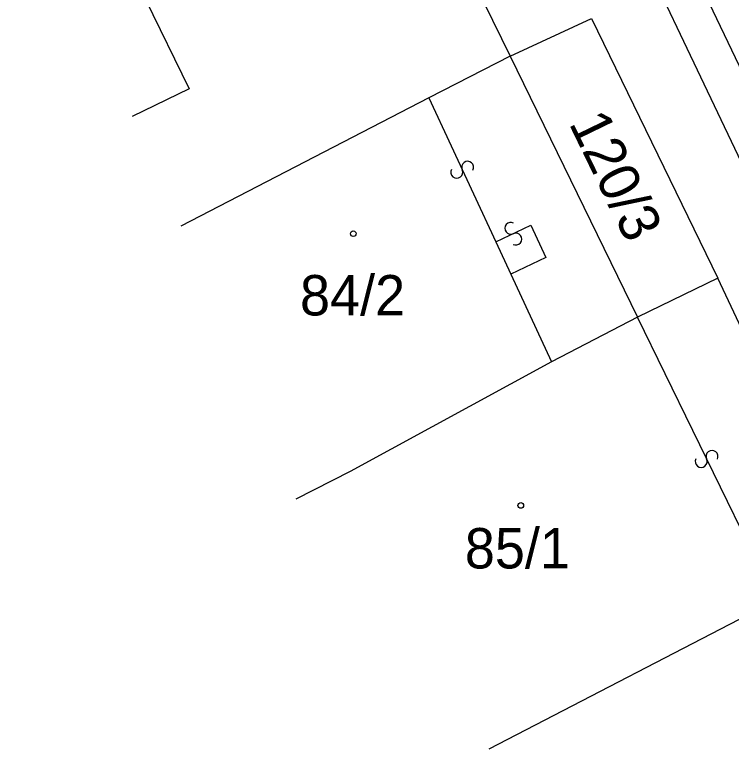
# Model space of a CAD drawing. Extents: x -595692 to -595466, y -1166896 to -1166788.
# Drawn here: x -595685.49 to -595663.31, y -1166868.26 to -1166845.7 of the extents above; entities that cross this region are included whole.
import ezdxf

# ---------------------------------------------------------------- set-up
doc = ezdxf.new("R2010")
doc.units = 0
doc.layers.add('DKM Holásky M 1_500', color=7, linetype='Continuous')

msp = doc.modelspace()

# ---------------------------------------------------------------- linework, layer by layer
at = {"layer": 'DKM Holásky M 1_500'}
for points in [[(-595644.41, -1166886.28), (-595673.03, -1166826.45)], [(-595674.15, -1166826.88), (-595645.66, -1166886.67)], [(-595677.24, -1166832.53), (-595670.16, -1166846.99)], [(-595685.49, -1166836.93), (-595680.09, -1166848)], [(-595670.16, -1166846.99), (-595667.64, -1166845.82)], [(-595667.64, -1166845.82), (-595663.73, -1166853.86)], [(-595670.16, -1166846.99), (-595672.67, -1166848.28)], [(-595670.16, -1166846.99), (-595666.22, -1166855.06)], [(-595680.09, -1166848), (-595681.855, -1166848.854)], [(-595672.67, -1166848.28), (-595680.344, -1166852.248)], [(-595672.67, -1166848.28), (-595670.6, -1166852.73)], [(-595670.6, -1166852.73), (-595669.52, -1166852.22)], [(-595669.52, -1166852.22), (-595669.05, -1166853.22)], [(-595670.6, -1166852.73), (-595670.14, -1166853.73)], [(-595669.05, -1166853.22), (-595670.14, -1166853.73)], [(-595670.14, -1166853.73), (-595668.88, -1166856.45)], [(-595663.73, -1166853.86), (-595666.22, -1166855.06)], [(-595659.61, -1166862.62), (-595663.73, -1166853.86)], [(-595666.22, -1166855.06), (-595668.88, -1166856.45)], [(-595661.94, -1166863.83), (-595666.22, -1166855.06)], [(-595668.88, -1166856.45), (-595675.11, -1166859.84)], [(-595675.11, -1166859.84), (-595676.789, -1166860.695)], [(-595661.94, -1166863.83), (-595670.82, -1166868.43)]]:
    msp.add_lwpolyline(points, dxfattribs=at)
for centre in [(-595675.01, -1166852.48), (-595669.829, -1166860.89)]:
    msp.add_circle(centre, 0.0875, dxfattribs=at)
for centre, radius, start, end in [((-595671.473, -1166850.424), 0.184, 331.9355, 204.4714), ((-595671.808, -1166850.576), 0.184, 152.1848, 23.7689), ((-595670.137, -1166852.313), 0.184, 62.2923, 294.7557), ((-595669.983, -1166852.647), 0.184, 242.6046, 114.7572), ((-595663.913, -1166859.371), 0.185, 333.5767, 205.8787), ((-595664.246, -1166859.529), 0.184, 153.4312, 25.4501)]:
    msp.add_arc(centre, radius, start, end, dxfattribs=at)

# ---------------------------------------------------------------- texts
msp.add_text('120/3', height=1.25, rotation=295.9024, dxfattribs=at).set_placement((-595668.354, -1166849.061))
for s, p in [('84/2', (-595676.66, -1166855.01)), ('85/1', (-595671.56, -1166862.84))]:
    msp.add_text(s, height=1.25, dxfattribs=at).set_placement(p)

doc.saveas('drawing.dxf')
